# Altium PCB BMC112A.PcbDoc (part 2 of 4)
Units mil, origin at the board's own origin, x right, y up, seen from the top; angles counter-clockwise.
Board outline 5600 x 6100 mil, 8 copper layers (Top Layer, Signal Layer 1, Signal Layer 2, Signal Layer 3, Signal Layer 4, Signal Layer 5, Signal Layer 6, Bottom Layer), stack 62.048 mil thick; 366 components, 158 nets, 872 pads, 1045 vias.
Unrouted connection lines stored in the file: 4.
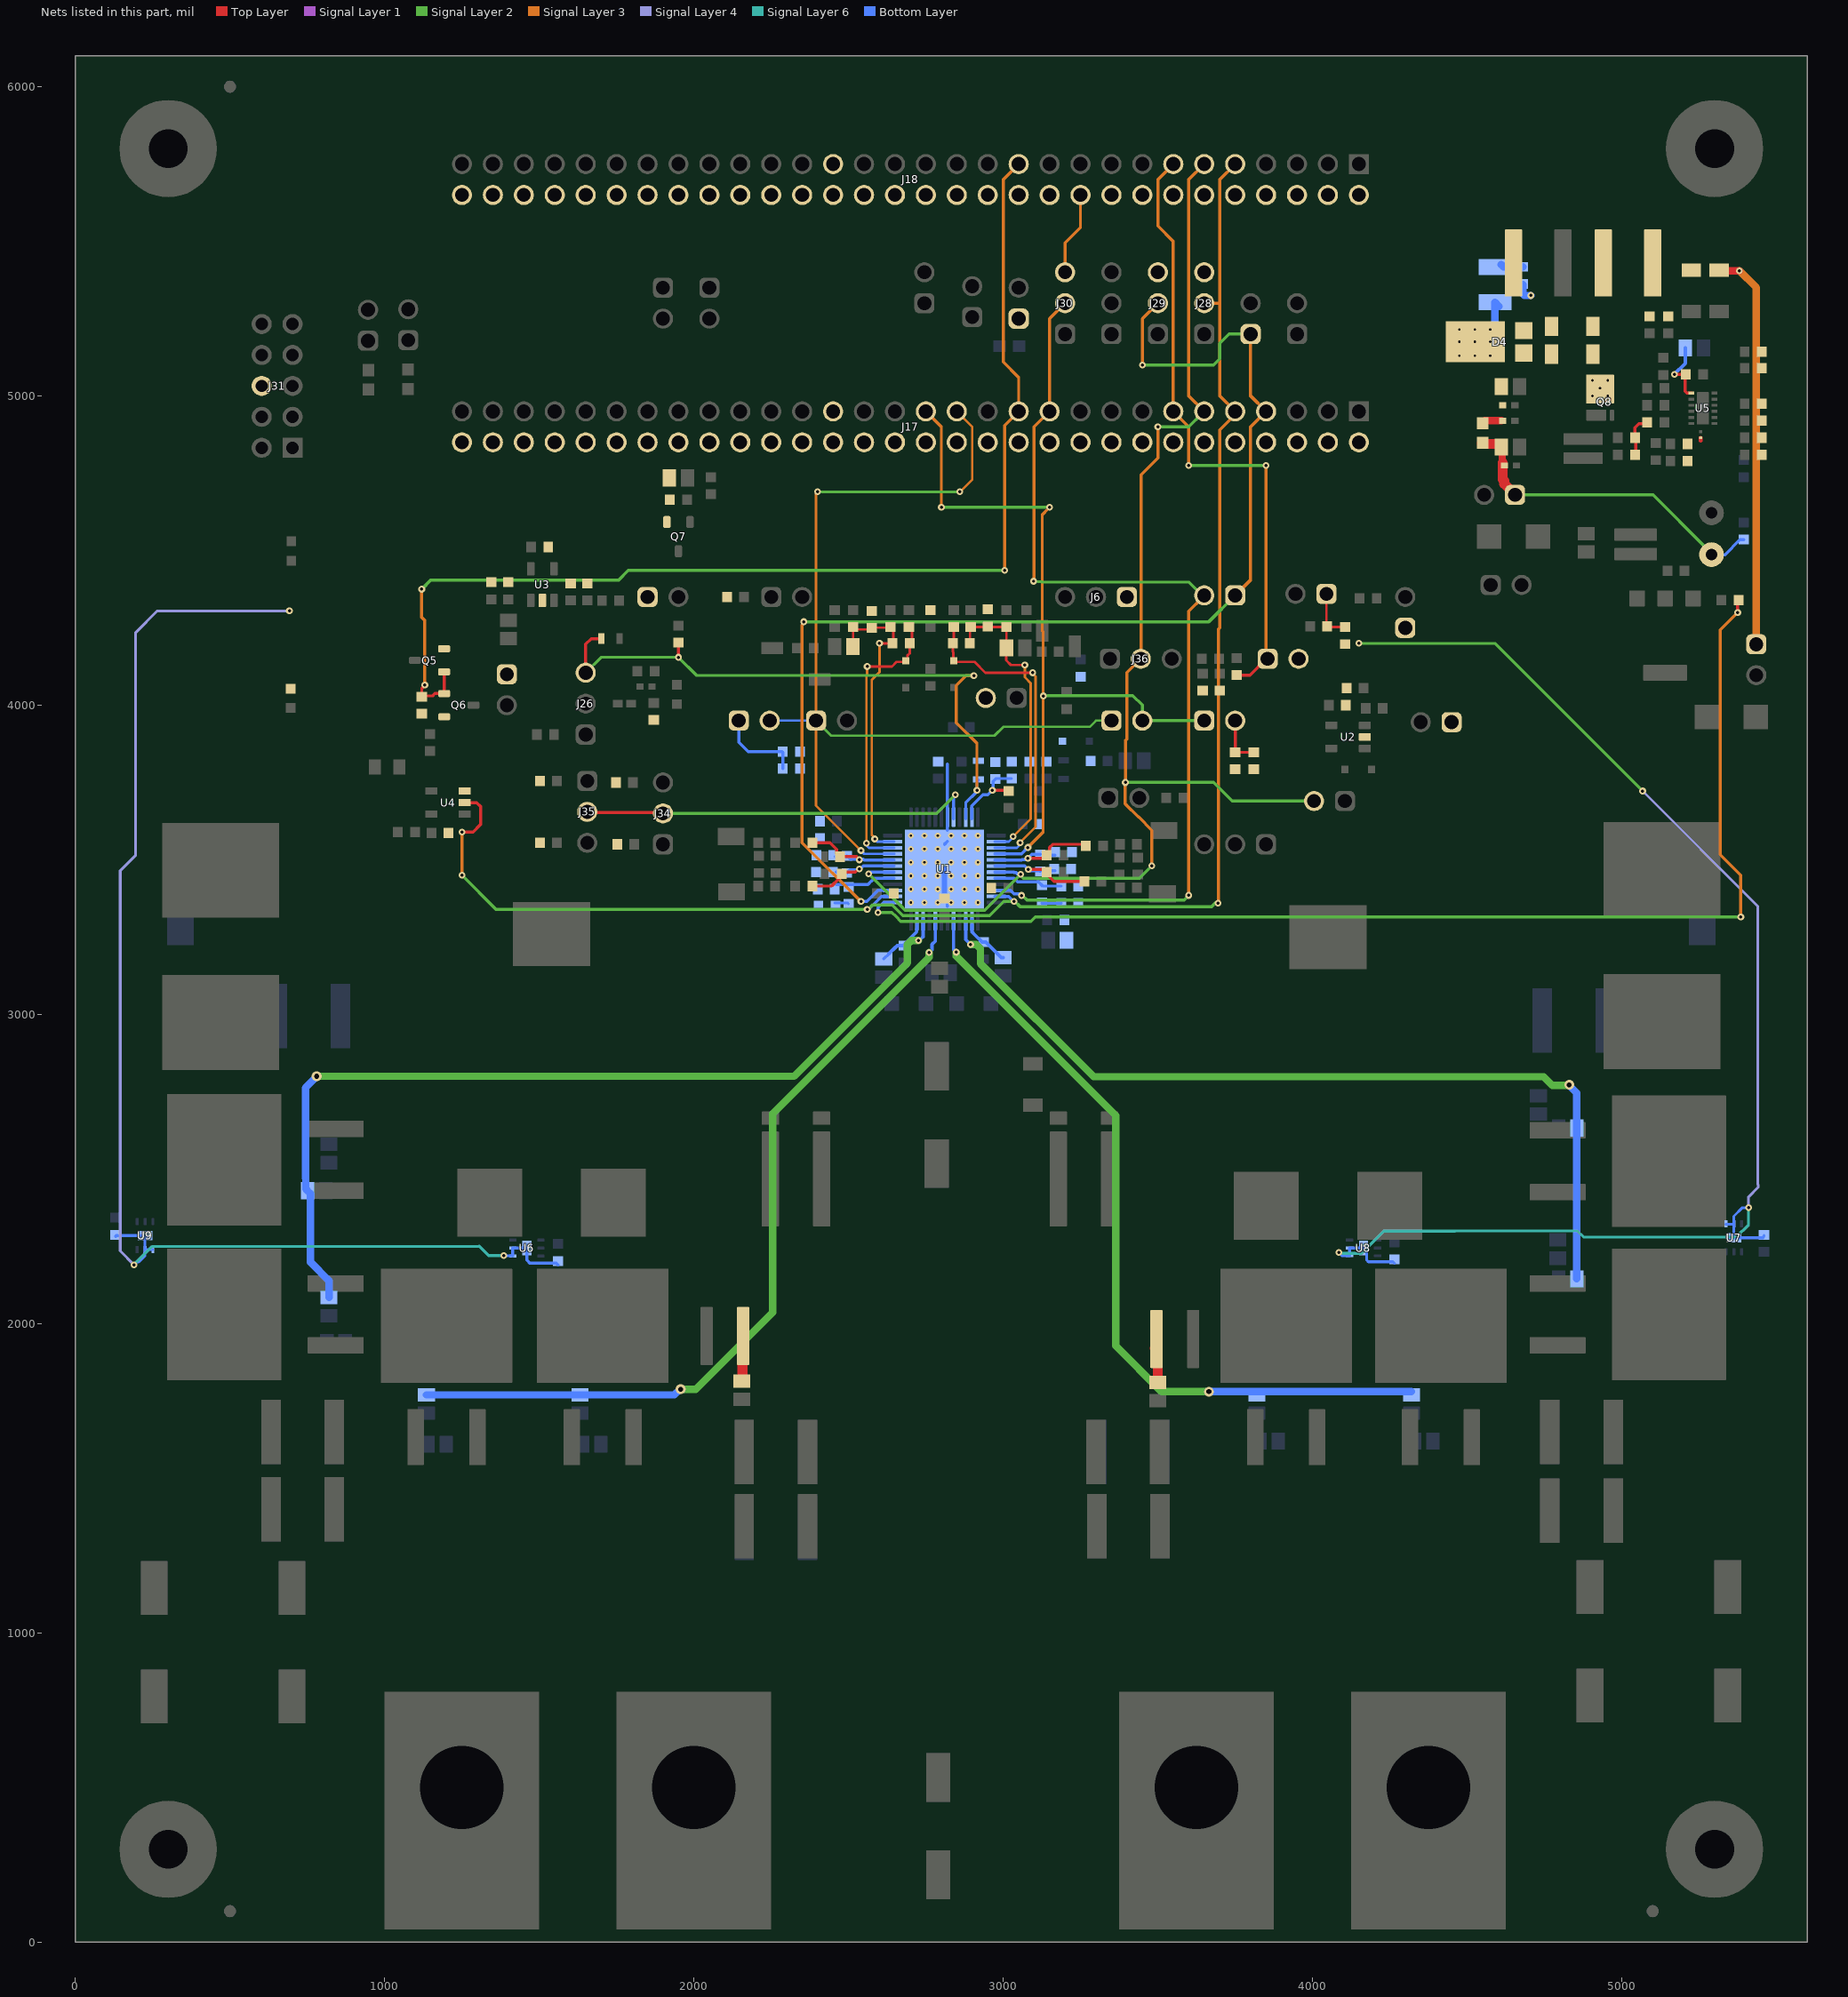
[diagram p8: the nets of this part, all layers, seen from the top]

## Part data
C1 C3 C16 C35 C79: library part CMP-0006844-4, "CAP, CERM, 1000 pF, 50 V, +/- 5%, X7R, AEC-Q200 Grade 1, 0603", Cap_Case=0603, Manufacturer=Kemet, Supplier Part Number 1=399-12989-1-ND, TempCo=X7R, Tolerance_%=5%, Value1=Unknown, Value2=50V, ValueDisplayed=1000pF
C2 C7 C10 C36 C85 C87 C98 C99 C100: library part CMP-0006727-4, "CAP, CERM, 0.01 uF, 100 V, +/- 10%, X7R, 0603", Cap_Case=0603, Manufacturer=AVX, Supplier Part Number 1=478-1205-1-ND, TempCo=X7R, Tolerance_%=10%, Value1="0.098 ohm", Value2=100V, ValueDisplayed=0.01uF
C4 C6: library part CMP-0007891-2, "CAP, CERM, 1 uF, 100 V, +/- 10%, X7S, 0805", Cap_Case=0805, Manufacturer=TDK, Supplier Part Number 1=445-5205-1-ND, TempCo=X7S, Tolerance_%=10%, Value1="0.008255 ohm", Value2=100V, ValueDisplayed=1uF
C5 C12 C14 C15 C37 C75 C88 C89 C90 C91 C92 C93 C94 C97 C101 C103: library part CMP-0007469-4, "CAP, CERM, 0.1 uF, 100 V, +/- 10%, X7R, 0603", Cap_Case=0603, Manufacturer=MuRata, Supplier Part Number 1=490-3285-1-ND, TempCo=X7R, Tolerance_%=10%, Value1=Unknown, Value2=100V, ValueDisplayed=0.1uF
C8 C9 C30 C34 C38 C39 C81 C82 C83 C84 C95 C96 C102 C106: library part CMP-0006841-4, "CAP, CERM, 100 pF, 50 V, +/- 5%, C0G/NP0, 0603", Cap_Case=0603, Manufacturer=Kemet, Supplier Part Number 1=399-1061-1-ND, TempCo=C0G/NP0, Tolerance_%=5%, Value1=Unknown, Value2=50V, ValueDisplayed=100pF
C11 C17: library part CMP-0007047-4, "CAP, CERM, 0.22 uF, 50 V, +/- 10%, X7R, 0603", Cap_Case=0603, Manufacturer=TDK, Supplier Part Number 1=445-7408-1-ND, TempCo=X7R, Tolerance_%=10%, Value1="0.021699 ohm", Value2=50V, ValueDisplayed=0.22uF
C13 C80 C107: library part CMP-0007867-2, "CAP, CERM, 2.2 uF, 16 V, +/- 10%, X7R, 0805", Cap_Case=0805, Manufacturer=TDK, Supplier Part Number 1=445-1420-1-ND, TempCo=X7R, Tolerance_%=10%, Value1="0.0049 ohm", Value2=16V, ValueDisplayed=2.2uF
C18 C32: library part CMP-0011313-2, "CAP, AL, 100 uF, 100 V, +/- 20%, 0.24 ohm, SMD", Cap_Case=LH0, Manufacturer=Chemi-Con, Supplier Part Number 1=565-2344-1-ND, Tolerance_%=20%, Value1="0.24 ohm", Value2=100V, ValueDisplayed=100uF
C19 C33: library part CMP-0007518-2, "CAP, CERM, 100 pF, 100 V, +/- 10%, C0G/NP0, 0805", Cap_Case=0805, Manufacturer=AVX, Supplier Part Number 1=478-3733-1-ND, TempCo=C0G/NP0, Tolerance_%=10%, Value1="0.356 ohm", Value2=100V, ValueDisplayed=100pF
C20 C21 C54 C55: library part CMP-0012273-3, "CAP, Aluminum Polymer, 180 uF, 50 V, +/- 20%, 0.019 ohm, SMD, 2-Leads, Dia 10.5mm, Pin Spacing 8mm SMD", Cap_Case=10x12.7mm, Manufacturer=Nichicon, Supplier Part Number 1=493-13774-1-ND, Tolerance_%=20%, Value1="0.019 ohm", Value2=50V, ValueDisplayed=180uF
C22 C23 C24 C25 C26 C27 C28 C29 C63 C64 C66 C67 C68 C69 C70 C71 C104 C105: library part CMP-0009385-2, "CAP, CERM, 4.7 uF, 100 V, +/- 20%, X7R, 2220", Cap_Case=2220, Manufacturer=TDK, Supplier Part Number 1=445-1450-1-ND, TempCo=X7R, Tolerance_%=20%, Value1="0.0015 ohm", Value2=100V, ValueDisplayed=4.7uF
C31: library part CMP-0008970-2, "CAP, CERM, 1 uF, 100 V, +/- 10%, X7R, 1206", Cap_Case=2220, Manufacturer=MuRata, Supplier Part Number 1=490-3909-1-ND, TempCo=X7R, Tolerance_%=10%, Value1=Unknown, Value2=100V, ValueDisplayed=1uF
C40: library part CMP-0064935-4, "CAP, CERM, 0.1 uF, 100 V,+/- 10%, X7R, AEC-Q200 Grade 1, 0603", Cap_Case=0603, Manufacturer=MuRata, Supplier Part Number 1=490-13420-1-ND, TempCo=X7R, Tolerance_%=10%, Value1=Unknown, Value2=100V, ValueDisplayed=0.1uF
C41: library part CMP-0007475-4, "CAP, CERM, 2200 pF, 100 V, +/- 10%, X7R, 0603", Cap_Case=0603, Manufacturer=MuRata, Supplier Part Number 1=490-1478-1-ND, TempCo=X7R, Tolerance_%=10%, Value1=Unknown, Value2=100V, ValueDisplayed=2200pF
C42 C43: library part CMP-0007468-5, "CAP, CERM, 0.01 uF, 100 V, +/- 10%, X7R, 0603", Cap_Case=0603, Manufacturer=MuRata, Supplier Part Number 1=GRM188R72A103KA01D-ND, TempCo=X7R, Tolerance_%=10%, Value1=Unknown, Value2=100V, ValueDisplayed=0.01uF
C44 C45 C46 C47: library part CMP-0008724-2, "CAP, CERM, 2.2 uF, 100 V, +/- 10%, X7S, 1206", Cap_Case=1206_180, Manufacturer=TDK, Supplier Part Number 1=445-5207-1-ND, TempCo=X7S, Tolerance_%=10%, Value1="0.005718 ohm", Value2=100V, ValueDisplayed=2.2uF
C48 C49: library part CMP-0007800-2, "CAP, CERM, 4.7 uF, 25 V, +/- 10%, X5R, 0805", Cap_Case=0805, Manufacturer=Kemet, Supplier Part Number 1=399-5505-1-ND, TempCo=X5R, Tolerance_%=10%, Value1=Unknown, Value2=25V, ValueDisplayed=4.7uF
C50 C51 C52 C53 C56 C57 C58 C59 C60 C61: library part CMP-0012265-3, "CAP, Aluminum Polymer, 39 uF, 80 V, +/- 20%, 0.035 ohm, AEC-Q200 Grade 1, D10xL10mm SMD", Cap_Case=10X10mm, Manufacturer=Chemi-Con, Supplier Part Number 1=565-4174-1-ND, Tolerance_%=20%, Value1="0.035 ohm", Value2=80V, ValueDisplayed=39uF
C62 C65 C72: library part CMP-0006674-2, "CAP, CERM, 0.01 uF, 50 V, +/- 10%, X7R, 0402", Cap_Case=0402, Manufacturer=MuRata, Supplier Part Number 1=490-4516-1-ND, TempCo=X7R, Tolerance_%=10%, Value1=Unknown, Value2=50V, ValueDisplayed=0.01uF
C73 C76: library part CMP-0080091-1, "CAP, CERM, 100 pF, 50 V,+/- 1%, C0G/NP0, 0603", Cap_Case=0603, Manufacturer=Kemet, Supplier Part Number 1=399-7819-1-ND, TempCo=C0G/NP0, Tolerance_%=1%, Value2=50V, ValueDisplayed=100pF
C74: library part CMP-0079607-1, "CAP, CERM, 1 µF, 16 V,+/- 10%, X7R, AEC-Q200 Grade 1, 0603", Cap_Case=0603, Manufacturer=TDK, Supplier Part Number 1=445-12539-1-ND, TempCo=X7R, Tolerance_%=10%, Value2=16V, ValueDisplayed=1µF
C77: library part CMP-0007094-5, "CAP, CERM, 0.22 uF, 50 V, +/- 10%, X7R, AEC-Q200 Grade 1, 0603", Cap_Case=0603, Manufacturer=TDK, Supplier Part Number 1=445-6926-1-ND, TempCo=X7R, Tolerance_%=10%, Value1="0.021699 ohm", Value2=50V, ValueDisplayed=0.22uF
C78: library part CMP-0007080-5, "CAP, CERM, 0.068 uF, 50 V, +/- 10%, X7R, AEC-Q200 Grade 1, 0603", Cap_Case=0603, Manufacturer=TDK, Supplier Part Number 1=445-5665-1-ND, TempCo=X7R, Tolerance_%=10%, Value1="0.035979 ohm", Value2=50V, ValueDisplayed=0.068uF
C86: library part CMP-0007100-4, "CAP, CERM, 0.033 uF, 100 V, +/- 10%, X7S, AEC-Q200 Grade 1, 0603", Cap_Case=0603, Manufacturer=TDK, Supplier Part Number 1=445-6935-1-ND, TempCo=X7S, Tolerance_%=10%, Value1="0.139637 ohm", Value2=100V, ValueDisplayed=0.033uF
CS1A CS1B CS2A CS2B: library part CMP-0003968-1, "Test Point, SMT", Manufacturer=Harwin, Supplier Part Number 1=952-2664-1-ND
D1 D2: library part CMP-0028782-2, "Diode, Schottky, 100 V, 1 A, AEC-Q101, SOD-123W", Manufacturer=Nexperia, Value1=1A, Value2=0.77V
D3: library part CMP-0076957-3, "Diode, Switching, 75 V, 0.3 A, SOD-523", Manufacturer="Micro Commercial Components", Value1=0.3A, Value2=1.25V
D4: library part CMP-0080010-2, "Diode, Schottky, 100 V, 5 A, AEC-Q101, PowerDI5", Manufacturer="Diodes Inc.", Value1=5A, Value2=0.71V
D5: library part CMP-0002893-1, "LED, Super Red, SMD", Color="super red", Manufacturer="Wurth Elektronik", Supplier Part Number 1=732-4979-1-ND, Value1=W, Value2=1.9V
D6 D7: library part CMP-0028401-2, "Diode, Schottky, 30 V, 2 A, SMA", Manufacturer="Diodes Inc.", Value1=2A, Value2=0.5V
D8: library part CMP-0085737-1, "Diode, Zener, 4.7 V, 300 mW, SOD-323", Manufacturer="ON Semiconductor", Power_W=300mW, Value1=0.3W
D9 D10 D13: library part CMP-0076911-2, "Diode, Switching, 75 V, 0.25 A, SOD-323", Manufacturer="Micro Commercial Components", Value1=0.25A, Value2=V
D11: library part CMP-0002894-2, "LED, Green, SMD", Color=green, Manufacturer="Wurth Elektronik", Value1=W, Value2=2V
D12: library part CMP-0002892-3, "LED, Yellow, SMD", Color=yellow, Manufacturer="Wurth Elektronik", Value1=W, Value2=2V
FID1 FID2 FID3 FID4 FID5 FID6: library part CMP-0077181-1, "Fiducial mark.  There is nothing to buy or mount.", Manufacturer=N/A
H1 H2 H3 H4: library part CMP-0003617-1, "Machine Screw, Round, #4-40 x 1/4, Nylon, Philips panhead", Manufacturer="B&F Fastener Supply", Supplier Part Number 1=H542-ND
H5 H6 H7 H8: library part CMP-0003610-1, "Standoff, Hex, 0.5\"L #4-40 Nylon", Manufacturer=Keystone, Supplier Part Number 1=36-1902C-ND
J1 J6 J13 J26 J28 J29 J30 J34 J35 J36: library part CMP-0054796-4, "Header, 2.54 mm, 3x1, Gold, TH", Manufacturer="Wurth Elektronik", Supplier Part Number 1=732-5316-ND
J2 J3 J4 J5 J7 J12 J14 J15 J16 J19 J20 J21 J22 J23 J24 J25 J27 J32 J33 J37 J38 J39 J40 J41 J42 J43 J44: library part CMP-0054794-2, "Header, 2.54 mm, 2x1, Gold, TH", Color=Black, Manufacturer="Wurth Elektronik", Supplier Part Number 1=732-5315-ND
J8 J9 J10 J11: library part CMP-0097398-1, "Banana Jack Connector Standard Banana Solder Lug", Digikey Part Number=36-6095-ND, Manufacturer="Keystone Electronics", Mouser Part Number=534-6095, Operating Temperature Range=to
J17 J18: library part CMP-0075499-1, "Header, 100mil, 30x2, Gold, TH", Manufacturer=Samtec
J31: library part CMP-0055448-2, "Header (shrouded), 100mil, 5x2, High-Temperature, Gold, TH", Manufacturer=3M, Supplier Part Number 1=MHC10K-ND
L1 L2: library part CMP-0064062-1, "Inductor, Shielded, Ferrite, 4.7 uH, 32 A, 0.0015 ohm, SMD", Manufacturer="Wurth Elektronik", Value1="0.0015 ohm", Value2=32A, ValueDisplayed=4.7uH
L3 L4: library part CMP-0095453-1, "22 µH Shielded Inductor 5.8 A 46.9mOhm Max Nonstandard", Digikey Part Number=2457-XGL6060-223MEC-ND, Manufacturer=Coilcraft, Operating Temperature Range=to, Self Resonant Frequency=9MHz, Test Frequency=1MHz, Tolerance_%=20%
L5: library part CMP-0003352-2, "Ferrite Bead, 120 ohm @ 100 MHz, 3 A, 0603", Manufacturer=MuRata, Supplier Part Number 1=490-3996-1-ND, Value1="0.025 ohm", Value2=3A, ValueDisplayed="120 ohm"
Logo5 Logo6: library part CMP-0074837-2, "IEC 61010-1 Hot Surface Warning", Manufacturer="Texas Instruments"
NT1 NT2: library part CMP-0078142-6, "Single point connection between nets.", Manufacturer=N/A
Q1 Q2 Q3 Q4 Q10 Q11 Q12 Q13: library part CMP-0087591-1, "N-Channel 100V 100A (Tc) 214W (Tc) Surface Mount D²PAK (TO-263AB)", Digikey Part Number=IPB042N10N3GATMA1CT-ND, Drain To Source Breakdown Voltage=100V, Input Capacitace At Vds="6320pF @ 50V", Manufacturer=Infineon, Max Forward Diode Voltage=1.2V, Mouser Part Number=726-IPB042N10N3GATMA, Operating Temperature Range="-55°C to +175°C", Power_W=214W, Pulse Drain Current=548A, Typ Forward Diode Voltage=1V
Q5 Q6 Q7: library part CMP-0000771-1, "MOSFET, N-CH, 60 V, 0.24 A, SOT-23", Alternate Manufacturer=None, Manufacturer=Vishay-Siliconix, Supplier Part Number 1=2N7002E-T1-E3CT-ND, Value1=1, Value2="0.4 nC"
Q8: library part CMP-0093385-1, "N-Channel 100 V 30A (Tc) 45.5W (Tc) Surface Mount PG-TSDSON-8-32", Digikey Part Number=448-IAUZ30N10S5L240ATMA1CT-ND, Drain To Source Breakdown Voltage=100V, Input Capacitace At Vds="640pF @ 50V", Manufacturer=Infineon, Mouser Part Number=726-IAUZ30N10S5L240A, Operating Temperature Range="-55°C to +175°C", Power_W=45.5W, Pulse Drain Current=120A, Typ Forward Diode Voltage=0.9V
Q9: library part CMP-0096318-1, "Small Signal low RDSon automotive Trans MOSFET N-CH 100V 1.1A 3-Pin SC-73 T/R", Digikey Part Number=1727-2725-1-ND, Drain To Source Breakdown Voltage=100V, Input Capacitace At Vds="112pF @ 50V", Manufacturer=Nexperia, Mouser Part Number=771-PMT560ENEAX, Operating Temperature Range="-55°C to +150°C", Power_W=750mW, Pulse Drain Current=4.4A, Typ Forward Diode Voltage=0.9V
R1 R8: library part CMP-0022536-4, "RES, 61.9 k, 1%, 0.1 W, AEC-Q200 Grade 0, 0603", Manufacturer=Vishay-Dale, Power_W=100mW, Supplier Part Number 1=541-61.9KHCT-ND, TempCo="100 ppm/C", Tolerance_%=1%, Value2=0.1W, Value_Code=61k9, ValueDisplayed=61.9k
R2 R88: library part CMP-0020834-3, "RES, 100 k, 1%, 0.125 W, AEC-Q200 Grade 0, 0805", Manufacturer=Vishay-Dale, Power_W=125mW, Supplier Part Number 1=541-100KCCT-ND, TempCo="100 ppm/C", Tolerance_%=1%, Value2=0.125W, Value_Code=100k
R3 R14 R17 R18 R31 R64 R82 R93 R94 R95 R96 R97 R98: library part CMP-0021998-4, "RES, 10.0 k, 1%, 0.1 W, AEC-Q200 Grade 0, 0603", Manufacturer=Vishay-Dale, Power_W=100mW, Supplier Part Number 1=541-10.0KHCT-ND, TempCo="100 ppm/C", Tolerance_%=1%, Value2=0.1W, Value_Code=10k0, ValueDisplayed=10.0k
R4 R43: library part CMP-0023085-5, "RES, 3.65 k, 1%, 0.1 W, 0603", Manufacturer=Yageo, Power_W=100mW, Supplier Part Number 1=311-3.65KHRCT-ND, TempCo="100 ppm/C", Tolerance_%=1%, Value2=0.1W, Value_Code=3k65, ValueDisplayed=3.65k
R5 R6 R12 R15: library part CMP-0022447-4, "RES, 49.9 k, 1%, 0.1 W, AEC-Q200 Grade 0, 0603", Manufacturer=Vishay-Dale, Power_W=100mW, Supplier Part Number 1=541-49.9KHCT-ND, TempCo="100 ppm/C", Tolerance_%=1%, Value2=0.1W, Value_Code=49k9, ValueDisplayed=49.9k
R7 R9 R50 R73 R74 R108 R109: library part CMP-0022204-4, "RES, 20.0 k, 1%, 0.1 W, AEC-Q200 Grade 0, 0603", Manufacturer=Vishay-Dale, Power_W=100mW, Supplier Part Number 1=541-20.0KHCT-ND, TempCo="100 ppm/C", Tolerance_%=1%, Value2=0.1W, Value_Code=20k0, ValueDisplayed=20.0k
R10 R49 R81 R85 R92: library part CMP-0022109-5, "RES, 1.00 k, 1%, 0.1 W, AEC-Q200 Grade 0, 0603", Manufacturer=Vishay-Dale, Power_W=100mW, Supplier Part Number 1=541-1.00KHCT-ND, TempCo="100 ppm/C", Tolerance_%=1%, Value2=0.1W, Value_Code=1k00, ValueDisplayed=1.00k
R11: library part CMP-0022324-4, "RES, 30.1 k, 1%, 0.1 W, AEC-Q200 Grade 0, 0603", Manufacturer=Vishay-Dale, Power_W=100mW, Supplier Part Number 1=541-30.1KHCT-ND, TempCo="100 ppm/C", Tolerance_%=1%, Value2=0.1W, Value_Code=30k1, ValueDisplayed=30.1k
R13 R19: library part CMP-0020518-3, "RES, 2.0, 5%, 0.125 W, AEC-Q200 Grade 0, 0805", Manufacturer=Vishay-Dale, Power_W=125mW, Supplier Part Number 1=541-2.0ACT-ND, TempCo="200 ppm/C", Tolerance_%=5%, Value2=0.125W, Value_Code=2R00, ValueDisplayed=2.0
R16: library part CMP-0022364-4, "RES, 38.3 k, 1%, 0.1 W, AEC-Q200 Grade 0, 0603", Manufacturer=Vishay-Dale, Power_W=100mW, Supplier Part Number 1=541-38.3KHCT-ND, TempCo="100 ppm/C", Tolerance_%=1%, Value2=0.1W, Value_Code=38k3, ValueDisplayed=38.3k
R20: library part CMP-0022587-4, "RES, 750 k, 1%, 0.1 W, AEC-Q200 Grade 0, 0603", Manufacturer=Vishay-Dale, Power_W=100mW, Supplier Part Number 1=541-750KHCT-ND, TempCo="100 ppm/C", Tolerance_%=1%, Value2=0.1W, Value_Code=750k
R21 R32: library part CMP-0001578-1, "1 mOhms ±2% 4W Chip Resistor Wide 3518 (9045 Metric), 1835 Current Sense, Moisture Resistant Metal Foil", Digikey Part Number=FC4L90R001GERCT-ND, Manufacturer=Ohmite, Mouser Part Number=588-FC4L90R001GER, Operating Temperature Range="-55°C to +155°C", Power_W=4W, TempCo=100ppm/°C, Tolerance_%=2%
R22 R27 R28 R30 R37 R38 R39 R41: library part CMP-0021009-3, "RES, 1.00, 1%, 0.125 W, AEC-Q200 Grade 0, 0805", Manufacturer=Vishay-Dale, Power_W=125mW, Supplier Part Number 1=72M6849, TempCo="100 ppm/C", Tolerance_%=1%, Value2=0.125W, Value_Code=1R00, ValueDisplayed=1.00
R23 R34: library part CMP-0015024-3, "RES, 10.0, 1%, 1 W, AEC-Q200 Grade 0, 1218", Manufacturer=Vishay-Dale, Power_W=1W, Supplier Part Number 1=RCL10.0ACT-ND, TempCo="100 ppm/C", Tolerance_%=1%, Value_Code=10R0, ValueDisplayed=10.0
R24 R25 R26 R29 R33 R35 R36 R40 R75: library part CMP-0021283-3, "RES, 49.9 k, 1%, 0.125 W, AEC-Q200 Grade 0, 0805", Manufacturer=Vishay-Dale, Power_W=125mW, Supplier Part Number 1=541-49.9KCCT-ND, TempCo="100 ppm/C", Tolerance_%=1%, Value2=0.125W, Value_Code=49k9, ValueDisplayed=49.9k
R42: library part CMP-0022374-4, "RES, 3.24 k, 1%, 0.1 W, AEC-Q200 Grade 0, 0603", Manufacturer=Vishay-Dale, Power_W=100mW, Supplier Part Number 1=541-3.24KHCT-ND, TempCo="100 ppm/C", Tolerance_%=1%, Value2=0.1W, Value_Code=3k24, ValueDisplayed=3.24k
R44 R106: library part CMP-0025874-4, "RES, 0, 5%, 0.1 W, AEC-Q200 Grade 0, 0603", Manufacturer=Panasonic, Power_W=100mW, Supplier Part Number 1=P0.0GCT-ND, TempCo="600 ppm/C", Tolerance_%=5%, Value2=0.1W, Value_Code=0000, ValueDisplayed=0
R45: library part CMP-0022228-4, "RES, 23.2 k, 1%, 0.1 W, AEC-Q200 Grade 0, 0603", Manufacturer=Vishay-Dale, Power_W=100mW, Supplier Part Number 1=541-23.2KHCT-ND, TempCo="100 ppm/C", Tolerance_%=1%, Value2=0.1W, Value_Code=23k2, ValueDisplayed=23.2k
R46 R89: library part CMP-0022066-4, "RES, 15.0 k, 1%, 0.1 W, AEC-Q200 Grade 0, 0603", Manufacturer=Vishay-Dale, Power_W=100mW, Supplier Part Number 1=541-15.0KHCT-ND, TempCo="100 ppm/C", Tolerance_%=1%, Value2=0.1W, Value_Code=15k0, ValueDisplayed=15.0k
R47: library part CMP-0022329-5, "RES, 316, 1%, 0.1 W, AEC-Q200 Grade 0, 0603", Manufacturer=Vishay-Dale, Power_W=100mW, Supplier Part Number 1=541-316HCT-ND, TempCo="100 ppm/C", Tolerance_%=1%, Value2=0.1W, Value_Code=316R, ValueDisplayed=316
R48: library part CMP-0022532-4, "RES, 60.4 k, 1%, 0.1 W, AEC-Q200 Grade 0, 0603", Manufacturer=Vishay-Dale, Power_W=100mW, Supplier Part Number 1=541-60.4KHCT-ND, TempCo="100 ppm/C", Tolerance_%=1%, Value2=0.1W, Value_Code=60k4, ValueDisplayed=60.4k
R51: library part CMP-0015029-2, "RES, 2.00, 1%, 0.5 W, AEC-Q200 Grade 0, 1210", Manufacturer=Panasonic, Power_W=500mW, Supplier Part Number 1=P17258CT-ND, TempCo="100 ppm/C", Tolerance_%=1%, Value2=0.5W, Value_Code=2R00, ValueDisplayed=2.00
R52 R53 R104 R107: library part CMP-0025885-5, "RES, 0, 5%, 0.1 W, 0603", Manufacturer=Yageo, Power_W=100mW, Supplier Part Number 1=311-0.0GRCT-ND, TempCo="200 ppm/C", Tolerance_%=5%, Value2=0.1W, Value_Code=0000, ValueDisplayed=0
R54 R71: library part CMP-0022736-4, "RES, 100, 1%, 0.1 W, 0603", Manufacturer=Yageo, Power_W=100mW, Supplier Part Number 1=311-100HRCT-ND, TempCo="100 ppm/C", Tolerance_%=1%, Value2=0.1W, Value_Code=100R, ValueDisplayed=100
R55: library part CMP-0022659-4, "RES, 95.3 k, 1%, 0.1 W, AEC-Q200 Grade 0, 0603", Manufacturer=Vishay-Dale, Power_W=100mW, Supplier Part Number 1=541-95.3KHCT-ND, TempCo="100 ppm/C", Tolerance_%=1%, Value2=0.1W, Value_Code=95k3, ValueDisplayed=95.3k
R56 R57 R58 R59: library part CMP-0022170-4, "RES, 1.00, 1%, 0.1 W, AEC-Q200 Grade 0, 0603", Manufacturer=Vishay-Dale, Power_W=100mW, Supplier Part Number 1=52K8059, TempCo="100 ppm/C", Tolerance_%=1%, Value2=0.1W, Value_Code=1R00, ValueDisplayed=1.00
R60: library part CMP-0015219-3, "RES, 0.03, 1%, 1 W, 0612", Manufacturer="Susumu Co Ltd", Power_W=1W, Supplier Part Number 1=PRL1632.030FCT-ND, TempCo="100 ppm/C", Tolerance_%=1%, Value_Code=R030, ValueDisplayed=0.03
R61 R110: library part CMP-0020448-3, "RES, 10, 5%, 0.125 W, AEC-Q200 Grade 0, 0805", Manufacturer=Vishay-Dale, Power_W=125mW, Supplier Part Number 1=541-10ACT-ND, TempCo="200 ppm/C", Tolerance_%=5%, Value2=0.125W, Value_Code=10R0, ValueDisplayed=10
R62 R63 R77 R78: library part CMP-0021991-4, "RES, 100, 1%, 0.1 W, AEC-Q200 Grade 0, 0603", Manufacturer=Vishay-Dale, Power_W=100mW, Supplier Part Number 1=541-100HCT-ND, TempCo="100 ppm/C", Tolerance_%=1%, Value2=0.1W, Value_Code=100R, ValueDisplayed=100
R65 R67 R72: library part CMP-0023142-5, "RES, 49.9 k, 1%, 0.1 W, 0603", Manufacturer=Yageo, Power_W=100mW, Supplier Part Number 1=311-49.9KHRCT-ND, TempCo="100 ppm/C", Tolerance_%=1%, Value2=0.1W, Value_Code=49k9, ValueDisplayed=49.9k
R66: library part CMP-0022510-4, "RES, 5.23 k, 1%, 0.1 W, AEC-Q200 Grade 0, 0603", Manufacturer=Vishay-Dale, Power_W=100mW, Supplier Part Number 1=541-5.23KHCT-ND, TempCo="100 ppm/C", Tolerance_%=1%, Value2=0.1W, Value_Code=5k23, ValueDisplayed=5.23k
R68: library part CMP-0096401-1, "Res Thick Film 0612 5.11Ohm 1% 1/2W ±100ppm/K Molded Paper T/R", Digikey Part Number=RCL06125R11FKEA-ND, Manufacturer="Vishay Dale", Mouser Part Number=71-RCL06125R11FKEA, Operating Temperature Range="-55°C to +155°C", Power_W=1W, TempCo=100ppm/°C, Tolerance_%=1%
R69: library part CMP-0021990-4, "RES, 100 k, 1%, 0.1 W, AEC-Q200 Grade 0, 0603", Manufacturer=Vishay-Dale, Power_W=100mW, Supplier Part Number 1=541-100KHCT-ND, TempCo="100 ppm/C", Tolerance_%=1%, Value2=0.1W, Value_Code=100k
R70: library part CMP-0022277-4, "RES, 2.49 k, 1%, 0.1 W, AEC-Q200 Grade 0, 0603", Manufacturer=Vishay-Dale, Power_W=100mW, Supplier Part Number 1=541-2.49KHCT-ND, TempCo="100 ppm/C", Tolerance_%=1%, Value2=0.1W, Value_Code=2k49, ValueDisplayed=2.49k
R76: library part CMP-0021087-3, "RES, 26.7 k, 1%, 0.125 W, AEC-Q200 Grade 0, 0805", Manufacturer=Vishay-Dale, Power_W=125mW, Supplier Part Number 1=541-26.7KCCT-ND, TempCo="100 ppm/C", Tolerance_%=1%, Value2=0.125W, Value_Code=26k7, ValueDisplayed=26.7k
R79: library part CMP-0022270-4, "RES, 2.10 k, 1%, 0.1 W, AEC-Q200 Grade 0, 0603", Manufacturer=Vishay-Dale, Power_W=100mW, Supplier Part Number 1=541-2.10KHCT-ND, TempCo="100 ppm/C", Tolerance_%=1%, Value2=0.1W, Value_Code=2k10, ValueDisplayed=2.10k
R80: library part CMP-0022453-4, "RES, 4.42 k, 1%, 0.1 W, AEC-Q200 Grade 0, 0603", Manufacturer=Vishay-Dale, Power_W=100mW, Supplier Part Number 1=541-4.42KHCT-ND, TempCo="100 ppm/C", Tolerance_%=1%, Value2=0.1W, Value_Code=4k42, ValueDisplayed=4.42k
R83: library part CMP-0023267-5, "RES, 75.0 k, 1%, 0.1 W, 0603", Manufacturer=Yageo, Power_W=100mW, Supplier Part Number 1=311-75.0KHRCT-ND, TempCo="100 ppm/C", Tolerance_%=1%, Value2=0.1W, Value_Code=75k0, ValueDisplayed=75.0k
R84: library part CMP-0022237-4, "RES, 24.9 k, 1%, 0.1 W, AEC-Q200 Grade 0, 0603", Manufacturer=Vishay-Dale, Power_W=100mW, Supplier Part Number 1=541-24.9KHCT-ND, TempCo="100 ppm/C", Tolerance_%=1%, Value2=0.1W, Value_Code=24k9, ValueDisplayed=24.9k
R86: library part CMP-0022449-4, "RES, 4.02 k, 1%, 0.1 W, AEC-Q200 Grade 0, 0603", Manufacturer=Vishay-Dale, Power_W=100mW, Supplier Part Number 1=541-4.02KHCT-ND, TempCo="100 ppm/C", Tolerance_%=1%, Value2=0.1W, Value_Code=4k02, ValueDisplayed=4.02k
R87: library part CMP-0025729-4, "RES, 1.0 k, 5%, 0.1 W, AEC-Q200 Grade 0, 0603", Manufacturer=Vishay-Dale, Power_W=100mW, Supplier Part Number 1=541-1.0KGCT-ND, TempCo="200 ppm/C", Tolerance_%=5%, Value2=0.1W, Value_Code=1k00, ValueDisplayed=1.0k
R90 R91: library part CMP-0022458-4, "RES, 4.99 k, 1%, 0.1 W, AEC-Q200 Grade 0, 0603", Manufacturer=Vishay-Dale, Power_W=100mW, Supplier Part Number 1=541-4.99KHCT-ND, TempCo="100 ppm/C", Tolerance_%=1%, Value2=0.1W, Value_Code=4k99, ValueDisplayed=4.99k
R99: library part CMP-0021998-4, "RES, 10.0 k, 1%, 0.1 W, AEC-Q200 Grade 0, 0603", Manufacturer=Vishay-Dale, Power_W=100mW, Supplier Part Number 1=541-10.0KHCT-ND, TempCo="100 ppm/C", Tolerance_%=1%, Value2=0.1W, Value_Code=10k0, ValueDisplayed=R95
R100: library part CMP-0022281-4, "RES, 2.74 k, 1%, 0.1 W, AEC-Q200 Grade 0, 0603", Manufacturer=Vishay-Dale, Power_W=100mW, Supplier Part Number 1=541-2.74KHCT-ND, TempCo="100 ppm/C", Tolerance_%=1%, Value2=0.1W, Value_Code=2k74, ValueDisplayed=2.74k
R101 R103: library part CMP-0082533-1, "RES, 4.99 k, 1%, 0.1 W, 0603", Manufacturer=Vishay-Dale, Power_W=100mW, Supplier Part Number 1=541-3985-1-ND, TempCo="100 ppm/C", Tolerance_%=1%, Value2=0.1W, Value_Code=4k99, ValueDisplayed=4.99k
R102: library part CMP-0025950-3, "RES, 100 k, 1%, 0.063 W, AEC-Q200 Grade 0, 0402", Manufacturer=Vishay-Dale, Power_W=63mW, Supplier Part Number 1=541-100KLCT-ND, TempCo="100 ppm/C", Tolerance_%=1%, Value2=0.063W, Value_Code=100k
R105: library part CMP-0022895-5, "RES, 1.00 k, 1%, 0.1 W, 0603", Manufacturer=Yageo, Power_W=100mW, Supplier Part Number 1=311-1.00KHRCT-ND, TempCo="100 ppm/C", Tolerance_%=1%, Value2=0.1W, Value_Code=1k00, ValueDisplayed=1.00k
SH-J1 SH-J2 SH-J3 SH-J4 SH-J5 SH-J6 SH-J7 SH-J8 SH-J9 SH-J10 SH-J11 SH-J12 SH-J13 SH-J14 SH-J15: library part CMP-0078738-1, "Single Operation 2.54mm Pitch Open Top Jumper Socket", Manufacturer=Harwin, Supplier Part Number 1=952-2881-ND
T1 T2 T3 T4: library part CMP-0075010-2, "Terminal 70A Lug", Manufacturer=Panduit, Supplier Part Number 1=CXS70-14-C-ND
TP1 TP2 TP3 TP4: library part CMP-0067619-1, "Natural PC Test Point Brass, SMT", Manufacturer=Harwin, Supplier Part Number 1=952-2665-1-ND
TP5 TP6: library part CMP-0078143-4, "TEST POINT.  No entry in BOM.", Manufacturer=N/A
U1: library part CMP-0097493-1, "Dual Channel 48V-12V Bidirectional PWM Controller", Manufacturer="Texas Instruments", Operating Temperature Range="-40°C to +125°C"
U2: library part CMP-0077859-1, "Automotive Qualified Precision, Zero-Crossover, 20MHz, 0.9pA Ib, RRIO, CMOS Operational Amplifier, DBV0005A (SOT-23-5)", Alternate Manufacturer="Texas Instruments", Alternate PartNumber=OPA320AQDBVTQ1
U3: library part CMP-0089971-1, "Automotive Catalog Single Differential Comparator 5-SOT-23 -40 to 125", Input Bias Current=0.0035uA, Input Offset Voltage=0.37mV, Manufacturer="Texas Instruments", Max Supply Voltage=36V, Min Supply Voltage=3V, Nominal Supply Current=210-275uA, Operating Temperature Range="-40°C to +125°C", Output Current Per Channel=20mA
U4: library part CMP-0051649-3, "Automotive Catalog Single Inverter, DBV0005A, LARGE T&R", Alternate Manufacturer="Texas Instruments", F @ Nom Voltage(Max)(Mhz)=150, Generic Part Number=SN74LVC1G04-Q1, ICC @ Nom Voltage(Max)(mA)=0.01, Operating Temperature Range="-40 to 125 C", Rating=Automotive, tpd @ Nom Voltage(Max)(ns)=7.5,5.2,4.2,3.7, Voltage(Nom)(V)=1.8,2.5,3.3,5
U5: library part CMP-0860750-2, "2.2-MHz Wide VIN 65-V Non-synchronous Boost/SEPIC/Flyback Controller with Dual Random Spread Spectrum, DSS0012B (WSON-12)", Alternate Manufacturer="Texas Instruments", Alternate PartNumber=LM5156DSST
U6 U7 U8 U9: library part CMP-0860728-1, "1.6V-Capable Temperature Sensor Switch with Factory Programmed Trip Points, NGF0006A (WSON-6)", Alternate Manufacturer="Texas Instruments", Operating Temperature Range="-40 to 150 C", PartNumber=LM26LVCISD-145/NOPB, Rating=Catalog
ZZ1: library part CMP-0077236-1
ZZ2: library part CMP-0077237-1
ZZ3: library part CMP-0077238-1
ZZ4 ZZ5 ZZ6 ZZ7 ZZ8 ZZ9 ZZ11 ZZ12 ZZ13 ZZ14 ZZ15 ZZ16 ZZ17 ZZ18 ZZ19: library part CMP-0077238-1, "These assemblies must comply with workmanship standards IPC-A-610 Class 2, unless otherwise specified."

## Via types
v1: diameter 32, hole 16, Top Layer to Bottom Layer, tented both sides, 330 vias
v2: diameter 32, hole 16, Top Layer to Bottom Layer, 240 vias
v3: diameter 22, hole 10, Top Layer to Bottom Layer, tented both sides, 222 vias
v4: diameter 24, hole 8, Top Layer to Bottom Layer, 192 vias
v5: diameter 19.68, hole 7.87, Top Layer to Bottom Layer, tented both sides, 36 vias
v6: diameter 24, hole 8, Top Layer to Bottom Layer, tented both sides, 14 vias
v7: diameter 24, hole 10, Top Layer to Bottom Layer, tented both sides, 7 vias
v8: diameter 19.68, hole 7.87, Top Layer to Bottom Layer, 3 vias
v9: diameter 22, hole 8, Top Layer to Bottom Layer, tented both sides, 1 vias

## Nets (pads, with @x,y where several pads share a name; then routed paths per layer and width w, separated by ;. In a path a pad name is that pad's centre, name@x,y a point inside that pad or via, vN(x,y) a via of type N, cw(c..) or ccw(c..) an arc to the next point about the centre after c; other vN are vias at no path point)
AGND: C1.2 C2.1 C3.1 C4.2 C6.2 C8.2 C9.2 C10.2 C12.2 C14.2 C15.2 C16.2 C30.2 C34.2 C35.1 C38.2 C39.2 C75.2 C88.2 C89.2 C90.1 C91.2 C92.2 C93.1 C94.1 C95.2 C96.2 C97.2 C101.2 C102.2 C103.2 C106.2 D8.2 D11.1 J3.1 J4.1 J5.1 J6.1 J14.1 J17.2 J17.4 J17.6 J17.8 J17.10 J17.12 J17.14 J17.16 J17.18 J17.20 J17.22 J17.24 J17.26 J17.28 J17.30 J17.32 J17.34 J17.35 J17.36 J17.38 J17.40 J17.42 J17.44 J17.46 J17.48 J17.50 J17.52 J17.54 J17.56 J17.58 J17.60 J18.2 J18.4 J18.6 J18.8 J18.10 J18.12 J18.14 J18.16 J18.18 J18.20 J18.22 J18.24 J18.26 J18.28 J18.30 J18.32 J18.34 J18.35 J18.36 J18.38 J18.40 J18.42 J18.44 J18.46 J18.48 J18.50 J18.52 J18.54 J18.56 J18.58 J18.60 J28.3 J29.3 J30.3 J31.6 J33.2 J37.2 J43.1 NT1.1 Q5.2 Q6.2 Q7.2 R3.1 R4.2 R5.1 R6.1 R9.1 R12.1 R14.1 R16.1 R17.2 R31.1 R43.1 R44.1 R47.1 R48.1 R49.1 R50.1 R55.1 R79.2 R80.2 R86.1 R100.1 R106.2 R109.1 U1.43 U1.49 U2.2 U3.2 U4.3 U6.1 U6.2 U6.7 U7.1 U7.2 U7.7 U8.1 U8.2 U8.7 U9.1 U9.2 U9.7 | length 9525.6
  Top Layer w10: C90.1@4105,3997.44 C90.1@4107.56,4000
  Signal Layer 2 w9: v3(4150,4200) 4590,4200 5065,3725 5070,3725 v3@5072.8,3727.8
  Signal Layer 3 w9: J30.3@3200,5400 3200,5495 3250,5545 J18.20@3250,5650
  Signal Layer 4 w9: v3(190,2190) 145,2235 145,3465 195,3515 195,4235 265,4305 v3(691.93,4305) ; v3(5067.5,3722.5) 5440,3350 5440,2450 5441.27,2448.73 5441.27,2441.27 5410,2410 v3(5410,2375)
  Signal Layer 6 w9: v3(190,2190) 190,2191.27 248.73,2250 1306.15,2250 ; 4460,2300 4856.48,2300 4876.48,2280 5370.43,2280 5410,2319.57 v3(5410,2375)
  Signal Layer 6 w10: 1306.15,2250 1336.15,2220 v3(1385,2220) ; v3(4085,2230) 4087.28,2227.72 4159.02,2227.72 4230.8,2299.5 4460,2299.5
  Bottom Layer w9: v3(190,2190) 200,2200 205,2200 225,2220 U9.7@225,2285 ; U9.2@225.28,2239.72 U9.1@250.59,2239.72 ; U8.7@4165,2245 4175.26,2234.74 4175.26,2205.27 4180.54,2200 4260,2200 C103.2@4265,2195 ; U7.1@5336.85,2321.7 5358.3,2321.7 U7.2@5360,2320 ; U7.7@5362.34,2277.72 U7.7@5362.44,2277.72 ; U7.2@5362.34,2322.99 5362.34,2347.34 5390,2375 v3(5410,2375) ; U7.7@5362.44,2276.42 U7.7@5362.44,2277.72 ; U7.2@5362.44,2321.7 U7.7@5362.44,2277.72 ; C101.2@5460,2285 5457.28,2277.72 U7.7@5362.44,2277.72
  Bottom Layer w10: C89.2@130,2282.44 132.56,2285 U9.7@225,2285 ; v3(1385,2220) 1385.59,2219.41 U6.1@1414.45,2219.41 ; U6.1@1414.45,2218.82 U6.1@1414.45,2219.41 ; U6.7@1459.72,2244.41 1459.72,2205.28 1470,2195 1555,2195 C92.2@1560,2190 ; U6.7@1460,2245 1429.96,2245 1429.45,2244.49 1414.53,2244.49 U6.2@1414.45,2244.41 U6.1@1414.45,2219.41 ; U1.49@2810,3391.26 2820,3381.26 NT1.1@2820,3350 ; U1.49@2810,3550 U1.49@2819.84,3559.84 ; 2819.84,3809.62 2819.84,3632.4 2819.84,3595.16 U1.49@2820,3595 ; v3@4084.41,2230.59 v3(4085,2230) 4095,2220 ; 4095.59,2219.41 U8.1@4119.72,2219.41 ; U8.1@4120,2220 4119.72,2220.28 U8.2@4119.72,2245 U8.7@4165,2245
  Bottom Layer w18: U1.49@2810,3391.26 2810,3430.63 U1.49@2810,3470
  other v5: 2701.73,3361.73 2745.04,3361.73 2788.35,3361.73 2831.65,3361.73 2874.96,3361.73 2918.27,3361.73 2701.73,3405.04 2745.04,3405.04 2788.35,3405.04 2831.65,3405.04 2874.96,3405.04 2918.27,3405.04 2701.73,3448.35 2745.04,3448.35 2788.35,3448.35 2831.65,3448.35 2874.96,3448.35 2918.27,3448.35 2701.73,3491.65 2745.04,3491.65 2788.35,3491.65 2831.65,3491.65 2874.96,3491.65 2918.27,3491.65 2701.73,3534.96 2745.04,3534.96 2788.35,3534.96 2831.65,3534.96 2874.96,3534.96 2918.27,3534.96 2701.73,3578.27 2745.04,3578.27 2788.35,3578.27 2831.65,3578.27 2874.96,3578.27 2918.27,3578.27
AGND2: C76.2 C77.2 C79.2 NT2.2 R66.1 R67.1 R69.1 R70.1 R104.2 | length 10
  Top Layer w12: 5255,4855 NT2.2@5255,4865
CFG: J34.2 J35.2 U1.44 | length 1301.8
  Top Layer w9.8: J35.2@1655,3655 1657.5,3652.5 1902.5,3652.5 J34.2@1905,3650
  Signal Layer 2 w9.8: J34.2@1900,3650 2785,3650 v3(2845,3710)
  Bottom Layer w9.8: U1.44@2839.53,3632.4 2839.53,3704.53 v3(2845,3710)
CSA1: C7.1 C8.1 R56.1 R96.1 U1.32 | length 381.3
  Top Layer w9.8: R96.1@2385,3555 2440,3555 2461.71,3533.29 2461.71,3520.85 R56.1@2472.56,3510 2483.41,3510.91 2525.7,3510.91 2529.7,3506.92 2531.8,3502.71 2532.93,3501.58 2534.26,3500.25 v3(2535,3500)
  Signal Layer 1 w9.8: v3@2531.73,3496.96 v3@2535,3500.23
  Bottom Layer w9.8: C8.1@2457.56,3510 C7.1@2495,3510 ; C7.1@2495,3512.56 2505.79,3501.77 2535,3501.77 2548.23,3501.77
  Bottom Layer w10: 2548.23,3501.77 2550.47,3499.53 U1.32@2647.6,3499.53
CSA2: C34.1 C36.2 R58.1 R98.1 U1.5 | length 406.3
  Top Layer w9.8: v3(3080,3505) 3130,3505 R58.1@3140,3515 3150,3525 3150,3540 3160,3550 3260,3550 R98.1@3265,3545
  Bottom Layer w9.8: U1.5@2972.4,3499.53 3059.53,3499.53 ; 3060,3500 3075,3500 v3(3080,3505) 3092.56,3517.56 C36.2@3120,3517.56 ; C36.2@3130,3515 C34.1@3167.44,3515
CSB1: C7.2 C9.1 R57.1 R97.1 U1.31 | length 378
  Top Layer w10: R97.1@2385,3415 2387.56,3415 2445,3415 2466.81,3436.81 2466.81,3449.25 2477.56,3460 2521.75,3460 2531.75,3470 v3(2535,3470)
  Bottom Layer w10: C9.1@2460,3460 2492.44,3460 C7.2@2495,3457.44 2505.75,3468.19 2533.19,3468.19 v3(2535,3470) 2538.25,3470 2548.09,3479.84 U1.31@2647.6,3479.84
CSB2: C30.1 C36.1 R59.1 R99.1 U1.6 | length 390.5
  Top Layer w9.8: v3(3081.5,3468.5) 3136.5,3468.5 3140,3465 3150,3455 3150,3445 3164.7,3430.3 R99.1@3259.7,3430.3
  Bottom Layer w9.8: U1.6@2972.4,3479.84 3060.16,3479.84 ; 3060,3480 3070,3480 3085,3465 3117.44,3465 C36.1@3120,3462.44 ; C36.1@3131.83,3465 3165,3465 C30.1@3167.44,3465
DEM: J17.23 J18.23 Q5.1 Q6.1 R12.2 | length 3792
  Top Layer w9.8: v3@1130,4070 v3(1130,4065) 1130,4063.62 1120,4053.62 1120,4030 1155,4030 1162.4,4037.4 Q6.1@1192.4,4037.4 ; Q6.1@1190,4035 Q6.1@1192.4,4037.4 ; Q5.1@1192.24,4107.6 1192.5,4107.34 1192.5,4037.5 Q6.1@1192.4,4037.4
  Signal Layer 2 w10: v3(1120,4375) 1150,4405 1756.85,4405 1787.98,4436.13 v3(3005,4436.13)
  Signal Layer 3 w10: v3(1120,4375) 1120,4283.76 1130,4273.76 v3(1130,4065) ; v3(3005,4436.13) 3004.65,4436.48 3004.65,4904.65 J17.23@3050,4950 3050,5060 3000,5110 3000,5700 J18.23@3050,5750
DIR: J17.9 J18.9 J28.2 U1.11 U1.26 U4.2 | length 5544.9
  Top Layer w10: v3@1251,3591 v3(1250,3590) 1285.51,3590 1309.86,3614.35 1309.86,3673.11 1297.97,3685 U4.2@1259.13,3685
  Signal Layer 2 w10: v3(1250,3450) 1360,3340 v3(2560,3340) 2563.25,3340 2577.12,3353.87 2640.85,3353.87 2660.86,3333.86 2675.72,3319 2679.37,3319 2956.3,3319 3002.3,3365 v3(3035,3365) 3038.25,3365 3054.37,3348.87 3673.87,3348.87 3685.86,3360.86 3694.14,3360.86 v3(3695,3360)
  Signal Layer 3 w10: v3(1250,3450) v3(1250,3590) ; J28.2@3650,5300 3700,5300 ; v3(3695,3360) 3695.35,3360.35 3695.35,4245.35 3700,4250 3700,4890 3750,4940 J17.9@3750,4950 3700,5000 3700,5300 ; J18.9@3750,5750 3700,5700 3700,5300
  Bottom Layer w10: v3(2560,3340) 2565,3340 2606.42,3381.42 U1.26@2647.6,3381.42 ; U1.11@2972.4,3381.42 3017.59,3381.42 v3@3034.01,3365
DT/SD: J26.3 R9.2 R10.2 R108.1 U1.46 | length 2076.4
  Top Layer w9.8: v3(1950,4155) R10.2@1950,4202.44 R10.2@1950,4205
  Top Layer w10: J26.3@1650,4105 1650,4197.12 1668.02,4215.14 1698.5,4215.14 R108.1@1702.44,4215.14
  Signal Layer 2 w9.8: J26.3@1650,4105 1700,4155 v3@1945,4155 ; v3(1950,4155) 2008.86,4096.14 2903.86,4096.14 v3(2905,4095)
  Signal Layer 3 w9.8: v3(2905,4095) 2879.74,4095 2848.56,4063.83 2848.56,3943.64 2915,3877.2 v3(2915,3725)
  Bottom Layer w9.8: U1.46@2878.9,3632.4 2878.9,3684.22 2915,3720.32 2915,3753.5 R9.2@2920,3758.5
EN1: J17.7 J23.1 J24.1 J29.2 U1.27 | length 4097.4
  Signal Layer 2 w10: v3(2355,4270) 3665,4270 J24.1@3750,4355 ; v3(3450,5100) 3680,5100 3700,5120 3700,5170 3730,5200 J23.1@3800,5200 J23.1@3805,5200
  Signal Layer 3 w10: v3(2355,4270) 2355,4265 2349.65,4259.65 2349.65,3921.7 2350,3921.35 2350,3555 v3(2540,3365) ; v3(3450,5100) 3450,5250 J29.2@3500,5300 ; J24.1@3750,4355 3800,4405 3800,4900 J17.7@3850,4950 3800,5000 J23.1@3800,5200 J23.1@3800,5205
  Bottom Layer w10: v3(2540,3365) 2558.75,3365 2594.85,3401.1 U1.27@2647.6,3401.1
EN2: J17.21 J24.2 J30.2 U1.10 | length 3160
  Signal Layer 2 w9: v3@3092.6,4399.56 3125.44,4399.56 3127.3,4397.7 3600.93,4397.7 3645.57,4353.07 J24.2@3663.64,4353.07
  Signal Layer 2 w10: v3(3059.38,3384.63) 3062.63,3384.63 3077.26,3370 3585,3370 v3(3600,3385)
  Signal Layer 3 w10: v3@3100,4400.8 3100,4900 J17.21@3150,4950 3150,5250 J30.2@3200,5300 ; v3(3600,3385) 3600,4303.78 J24.2@3645,4348.78
  Bottom Layer w10: U1.10@2972.4,3401.1 3023.96,3401.1 3035.06,3390 3054.01,3390 v3(3059.38,3384.63)
  other v3: 3098.18,4400.8
ERRHV: C83.1 C86.1 D9.2 U1.34 | length 901.3
  Top Layer w8: v3@2565,4125 2640,4125 2655,4140 D9.2@2680,4140 ; D9.2@2685,4145 2690,4150 2690,4160 2697.56,4167.56 C83.1@2697.56,4200 2705,4207.44 C86.1@2705,4245
  Signal Layer 3 w8: v3(2557.92,3553.9) 2557.92,4094.06 2560,4096.14 v3(2560,4125)
  Bottom Layer w8: v3(2557.92,3553.9) 2560,3551.82 2560,3545 2566.1,3538.9 U1.34@2647.6,3538.9
ERRLV: C84.2 C87.1 D10.2 U1.3 | length 1047
  Top Layer w8: D10.2@2840,4143.72 2839.08,4144.64 2839.08,4170.92 2837.44,4172.56 C84.2@2837.44,4200 2840,4202.56 C87.1@2840,4252.44 C87.1@2840,4255 ; D10.2@2845,4145 2850,4140 2907.44,4140 2942.44,4105 v3(3095,4105)
  Signal Layer 3 w8: v3(3054.38,3555.37) 3105,3605.99 3105,4093.31 3095,4103.31 v3(3095,4105)
  Bottom Layer w8: U1.3@2972.4,3538.9 3043.9,3538.9 3054.38,3549.38 v3(3054.38,3555.37)
FBHV: C83.2 R73.1 R75.1 R79.1 R83.2 U1.35 | length 1003.6
  Top Layer w8: R75.1@2514.53,4190 2515,4190.47 R73.1@2515,4250 ; R73.1@2515,4252.44 2522.44,4245 R79.1@2575,4245 ; R79.1@2575,4250 2575.47,4250.47 2639.53,4250.47 2645,4245 2645,4202.56 C83.2@2642.44,4200 ; v3(2600,4200) 2640,4200 C83.2@2645,4195
  Signal Layer 3 w8: v3(2584.61,3567.32) 2584.61,3571.11 2575,3580.72 2575,4082.04 2600,4107.04 v3(2600,4200)
  Bottom Layer w8: v3(2584.61,3567.32) 2584.61,3565.39 2591.42,3558.58 U1.35@2647.6,3558.58
FBLV: C84.1 R74.2 R76.2 R80.1 R84.2 U1.2 | length 984.7
  Top Layer w8: R84.2@2890,4255 R84.2@2892.56,4252.44 ; C84.1@2892.56,4200 R84.2@2892.56,4252.44 ; R76.2@3010,4170 3010,4145 3025,4130 v3(3070,4130) ; R74.2@3010,4250 3010.47,4249.53 R76.2@3010.47,4185 ; R74.2@3010,4252.44 R84.2@2892.56,4252.44
  Signal Layer 3 w8: v3(3032.22,3575.41) 3089.13,3632.31 3089.13,4071.14 3070,4090.26 v3(3070,4130)
  Bottom Layer w8: U1.2@2972.4,3558.58 3018.58,3558.58 3030,3570 3030,3573.18 v3(3032.22,3575.41)
HO1: R22.1 R30.1 U1.22 | length 2982.9
  Signal Layer 2 w24: v1(780,2800) 2323.66,2800 2690.45,3166.78 2690.45,3226.16 2703.21,3238.93 v3(2725.88,3238.93)
  Bottom Layer w11: v3@2734.77,3244.72 2741.1,3251.05 U1.22@2741.1,3307.6
  Bottom Layer w24: R30.1@750.47,2430 745,2435.47 745,2470 744.13,2470.87 744.13,2762.34 780,2798.21 v1(780,2800) ; R30.1@755,2425 760,2420 760,2198.69 820,2138.69 R22.1@820,2084.53
HO2: R37.1 R41.1 U1.15 | length 2875.5
  Signal Layer 2 w24: v3(2894.63,3226.28) 2912.54,3226.28 2926.53,3212.28 2926.53,3164.25 3292.47,2798.31 4747.78,2798.31 4776.1,2770 v1@4830,2770
  Bottom Layer w11: U1.15@2878.9,3307.6 2878.9,3242.01 v3(2894.63,3226.28)
  Bottom Layer w24: v1(4830,2772.44) 4830,2770.27 4854.53,2745.75 R41.1@4854.53,2652.44 ; R37.1@4854.53,2145 R41.1@4854.53,2650
IOUT1: J2.2 J16.1 J17.27 J21.1 U1.33 | length 3226.8
  Signal Layer 2 w8: J16.1@2395,3950 2443.71,3901.29 2971.81,3901.29 3000.52,3930 3279.79,3930 3299.79,3950 J21.1@3350,3950 ; v3(2400,4690) v3(2860,4690)
  Signal Layer 3 w8: J16.1@2395,3940 2395,3675 v3(2540,3530) ; J16.1@2395,3950 2395,4685 v3(2400,4690) ; J17.27@2850,4950 2900,4900 2900,4730 v3(2860,4690)
  Bottom Layer w8: J2.2@2245,3950 J16.1@2395,3950 ; v3(2540,3530) 2550.79,3519.21 U1.33@2647.6,3519.21
IOUT2: J7.1 J17.29 J21.2 U1.4 | length 2509.5
  Signal Layer 2 w9.8: v3(2800,4640) v3(3150,4640) ; v3@3129.38,4031.33 3419.16,4031.33 3450,4000.49 J21.2@3450,3950 J7.1@3650,3950
  Signal Layer 3 w9.8: J17.29@2750,4950 2800,4900 v3(2800,4640) ; v3(3080,3540) 3129.02,3589.02 3129.02,4237.36 3126.23,4240.15 3126.23,4616.23 3146.02,4636.02 v3@3146.02,4638.98
  Bottom Layer w9.8: U1.4@2972.4,3519.21 3059.21,3519.21 v3(3080,3540)
  other v3: 3130,4030
IPK: C39.1 R11.1 R14.2 U1.47 | length 271.6
  Top Layer w9.8: v3(2965,3725) R11.1@3015,3725
  Bottom Layer w8: C39.1@2975,3762.44 R14.2@3027.35,3762.44
  Bottom Layer w9.8: U1.47@2898.58,3632.4 2898.58,3673.95 2934.63,3710 2949.91,3710 v3@2965,3725.09 ; v3(2965,3725) 2965,3728.3 2967.61,3730.91 2967.61,3753.57 C39.1@2974.98,3760.94
ISETA: J17.11 J18.11 J36.2 J42.2 U1.7 U1.30 | length 4365.3
  Signal Layer 2 w10: v3(2565,3455) 2668.27,3351.73 2683.13,3336.87 2940.46,3336.87 v3(3056.2,3452.61) 3056.2,3449.37 3065.57,3440 3440,3440 v3(3480,3480) ; v3(3395,3750) 3680,3750 3740,3690 J42.2@4005,3690 ; v3(3500,4900) 3600,4900 J17.11@3645,4945
  Signal Layer 3 w10: 3395,3680 3437.07,3637.93 3438.79,3637.93 3480.86,3595.86 3480,3595 v3(3480,3480) ; 3397.93,3677.93 3394.65,3681.21 3394.65,3749.65 v3(3395,3750) 3395,3885 3400,3889.98 3400,4105 J36.2@3445,4150 3445.35,4150.35 3445.35,4745.35 3500,4800 v3(3500,4900) ; J18.11@3650,5760 J18.11@3650,5750 3600,5700 3600,5000 J17.11@3650,4950 J17.11@3655,4950
  Bottom Layer w10: v3(2565,3455) 2570.16,3460.16 U1.30@2647.6,3460.16 ; U1.7@2972.4,3460.16 3034.79,3460.16 ; 3034.79,3458.25 3042.08,3458.25 3045.42,3454.91 3053.9,3454.91 v3(3056.2,3452.61)
ISETD: J17.13 J18.13 J33.1 R92.1 | length 2041.2
  Top Layer w10: R92.1@3750,4097.44 3797.64,4097.44 J33.1@3850.2,4150
  Signal Layer 2 w10: v3(3600,4775) v3(3850,4775)
  Signal Layer 3 w10: J17.13@3545,4945 J17.13@3550,4950 ; J18.13@3550,5750 3500,5700 3500,5550 3550,5500 J17.13@3550,4950 ; v3(3600,4775) 3600,4900 J17.13@3550,4950 ; J33.1@3850,4150 v3(3850,4775)
LDODRV: R71.2 U1.25 | length 3967.8
  Top Layer w9.8: v3(5375,4300) R71.2@5375,4350
  Signal Layer 2 w9.8: v3(2595,3330) 2639.59,3330 2653.5,3316.08 2668.36,3301.23 2669.62,3301.23 2993.11,3301.23 3070.15,3301.23 3089.85,3301.23 3103.62,3315 3105,3315 v3(5385,3315)
  Signal Layer 3 w9.8: v3(5375,4300) 5318.73,4243.73 5318.73,3516.27 5385,3450 v3(5385,3315)
  Bottom Layer w9.8: v3(2595,3330) 2595,3344.86 2611.87,3361.73 U1.25@2647.6,3361.73
LO1: R27.1 R28.1 U1.20 | length 2712.6
  Signal Layer 2 w24: v1(1957.31,1787.76) 2006.42,1787.76 2255,2036.34 2255,2679.41 2760.56,3184.97 v3@2760.56,3199.82
  Bottom Layer w11: v3(2760,3200) 2769.71,3209.71 2769.71,3223.03 2769.71,3226.28 2780.47,3237.04 U1.20@2780.47,3307.6
  Bottom Layer w24: R27.1@1135,1769.53 R28.1@1625.47,1769.53 ; R28.1@1631.77,1769.53 1936.9,1769.53 v1@1956.22,1788.85
LO2: R38.1 R39.1 U1.17 | length 2614.1
  Signal Layer 2 w24: v3(2848.56,3200.94) 2848.56,3187.85 3363.51,2672.91 3363.51,1928.57 3512.07,1780 v1(3665,1780)
  Bottom Layer w11: U1.17@2839.53,3307.6 2839.53,3209.98 v3(2848.56,3200.94)
  Bottom Layer w24: v1(3665,1780) R38.1@4320,1780
NetC2_2: C2.2 J2.1 R3.2 | length 276
  Bottom Layer w9.8: J2.1@2145,3950 2145,3880 2175,3850 2285,3850 R3.2@2287.44,3847.56 ; C2.2@2287.44,3795 R3.2@2287.44,3845.16
NetC3_2: C3.2 C5.2 U1.29 | length 196.1
  Bottom Layer w9.8: C3.2@2460,3420 2500,3420 2515,3420 2562.79,3420 2574.01,3431.23 2574.85,3431.23 2584.09,3440.47 U1.29@2647.6,3440.47
NetC5_1: C5.1 R4.1 | length 46.1
  Bottom Layer w8: R4.1@2455,3360 2497.44,3360 C5.1@2500,3357.44
NetC10_1: C10.1 J7.2 R31.2 | length 161.1
  Top Layer w10: R31.2@3750,3845 3752.56,3847.56 C10.1@3810,3847.56 ; R31.2@3750,3850 J7.2@3750,3950
NetC11_1: C11.1 R13.1 U1.23 | length 180.7
  Bottom Layer w10: R13.1@2613.98,3179.65 2614.25,3179.65 R13.1@2630.9,3196.31 ; C11.1@2678.98,3222.69 2678.98,3225.46 2702,3248.48 2702,3248.81 2711.66,3258.47 2711.83,3258.31 2720.51,3266.99 2720.51,3268.9 2720.51,3276.05 2721.42,3276.96 U1.23@2721.42,3302.68
  Bottom Layer w12: R13.1@2630.9,3196.31 2651.28,3216.69 2657.28,3222.69 C11.1@2678.98,3222.69
NetC14_1: C14.1 J12.1 R18.2 | length 162.1
  Top Layer w8: J12.1@4045,4360 4045,4257.56 R18.2@4047.56,4255 ; R18.2@4050,4255 4052.44,4252.56 C14.1@4105,4252.56
NetC17_1: C17.1 R19.1 U1.14 | length 157.6
  Bottom Layer w9.8: U1.14@2898.58,3307.6 U1.14@2898.97,3307.21
  Bottom Layer w11: U1.14@2898.74,3288.17 2898.97,3287.94 U1.14@2898.97,3272.07 ; U1.14@2898.74,3306.99 U1.14@2898.96,3307.21 ; U1.14@2898.99,3272.05 2898.99,3266.78 2907.96,3257.81 2931.98,3233.79 C17.1@2936.97,3233.79
  Bottom Layer w12: C17.1@2936.97,3233.79 2943.71,3233.79 2978.22,3199.28 2993.88,3183.62 R19.1@2999.78,3183.62
NetC19_1: C19.1 R23.1 | length 107.5
  Top Layer w32: C19.1@2155,1814.53 2157,1816.53 2157,1917 R23.1@2160,1920
NetC33_1: C33.1 R34.1 | length 114.6
  Top Layer w32: R34.1@3490,1920 3500,1910 C33.1@3500,1809.53
NetC35_2: C35.2 C37.1 U1.8 | length 225.6
  Bottom Layer w9.8: U1.8@2972.4,3440.47 3034.72,3440.47 3046.64,3428.56 3107.43,3428.56 3107.57,3428.41 3114.15,3428.41 3127.56,3415 C35.2@3187.44,3415
NetC37_2: C37.2 R43.2 | length 62.4
  Bottom Layer w9.8: C37.2@3125,3360 R43.2@3187.44,3360
NetC40_1: C40.1 R61.1 U5.1 | length 211.9
  Top Layer w9.8: v3(5170,5070) 5205,5070 5205,5015.13 5210.74,5009.39 U5.1@5225,5009.37
  Bottom Layer w12: v3(5170,5070) 5205.47,5105.47 R61.1@5205.47,5155
NetC41_1: C41.1 R51.1 | length 73.3
  Bottom Layer w24: R51.1@4610,5425 4617.68,5417.32 4679.76,5417.32 C41.1@4680,5417.56
NetC41_2: C41.2 C46.2 C47.2 D4.1 D4.2 L4.1 | length 58.5
  Bottom Layer w24: C41.2@4680,5360 4680,5330 4685,5325 v3(4706.41,5325)
NetC42_1: C42.1 C43.1 C44.2 C45.2 J41.1 L3.1 | length 1296.5
  Top Layer w24: C45.2@5315,5406.93 5316.93,5405 v3(5380,5405)
  Signal Layer 3 w24: v3@5380.11,5405.07 5435,5350.17 J41.1@5435,4197.06
NetC46_1: C46.1 C47.1 L3.2 Q8.5-6-7-8
  other v6: 4905,5000 4955,5000 4930,5025 4905,5050 4955,5050
NetC48_2: C48.2 C62.1 C65.1 D4.3 L5.2 R51.2 | length 175.3
  Top Layer w24: L5.2@4550,4910 L5.2@4550,4911.5 4550,4912.48 4557.52,4920 C65.1@4611.38,4920
  Bottom Layer w24: v6@4575,5220 4590,5235 R51.2@4590,5302.91 R51.2@4603.59,5289.32
  other v6: 4475,5130 4525,5130 4575,5130 4475,5175 4525,5175 4575,5175 4475,5215 4525,5215 4575,5215
NetC49_2: C49.2 C72.1 J38.1 L5.1 R63.2 TP5.1 | length 1082.3
  Top Layer w24: C49.2@4610,4835 4613.43,4831.57 4613.43,4775.19 4613.61,4775 C72.1@4615,4775
  Top Layer w32: L5.1@4547.74,4846.24 L5.1@4550,4848.5 4550,4847.52 4552.7,4844.82 4604.82,4844.82 C49.2@4605,4845 ; 4615,4785 4615,4775 4615,4730 4620,4725 4620,4715.13 4655,4680.13 J38.1@4655,4680 ; J38.1@4650,4680 J38.1@4655,4675
  Signal Layer 2 w10: J38.1@4655,4680 5101.5,4680 5271.5,4510 TP5.1@5290,4510
  Bottom Layer w10: TP5.1@5290,4486.71 5333.83,4486.71 5382.12,4535 R63.2@5395,4535
NetC73_1: C73.1 R53.1 R54.2 | length 136.2
  Top Layer w9.8: C73.1@5042.56,4810 5045,4812.44 R54.2@5045,4870 ; R54.2@5042.56,4865 5042.56,4897.56 5055,4910 R53.1@5080,4910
